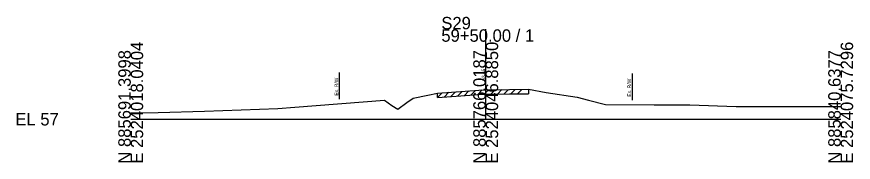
# Model space of a CAD drawing. Extents: x -26 to 163, y -10 to 4024.
# Drawn here: x -25.7 to 162.8, y 490.3 to 523.1 of the extents above; entities that cross this region are included whole.
import ezdxf

# ---------------------------------------------------------------- set-up
doc = ezdxf.new("R2010")
doc.units = 0
for name, color, linetype in [('RD_GPK_XS_Cell', 7, 'Continuous'), ('RD_XS_ExGround', 7, 'Continuous'), ('RD_XS_ExPaveRet', 7, 'Continuous'), ('RD_XS_ExRW', 7, 'Continuous'), ('RD_XS_TX_Elev_EX', 7, 'Continuous')]:
    doc.layers.add(name, color=color, linetype=linetype)

msp = doc.modelspace()

# ---------------------------------------------------------------- linework, layer by layer
at = {"layer": 'RD_GPK_XS_Cell'}
for p, q in [((80, 500), (80, 520.28)), ((0, 500), (80, 500)), ((80, 500), (160, 500))]:
    msp.add_line(p, q, dxfattribs=at)
at = {"layer": 'RD_XS_ExGround'}
for p, q in [((63.69, 504.78), (66.94, 505.42)), ((66.94, 505.42), (69.15, 505.92)), ((69.15, 505.92), (73.31, 506.18)), ((73.31, 506.18), (79.54, 506.64)), ((79.54, 506.64), (80, 506.65)), ((80, 506.65), (85.33, 506.72)), ((85.33, 506.72), (89.66, 506.76)), ((89.66, 506.76), (93.61, 506.05)), ((93.61, 506.05), (100.59, 505.02)), ((36.99, 502.76), (57.21, 504.34)), ((57.21, 504.34), (58.82, 503.14)), ((60.22, 502.25), (62.26, 503.75)), ((62.26, 503.75), (63.69, 504.78)), ((100.59, 505.02), (103.15, 504.31)), ((103.15, 504.31), (107.03, 503.34)), ((0, 501.47), (6.2, 501.52)), ((6.2, 501.52), (16.64, 501.86)), ((16.64, 501.86), (33.12, 502.41)), ((33.12, 502.41), (36.99, 502.76)), ((58.82, 503.14), (60.22, 502.25)), ((107.03, 503.34), (117.98, 503.29)), ((117.98, 503.29), (125.97, 503.29)), ((125.97, 503.29), (136.48, 502.85)), ((136.48, 502.85), (160, 502.89))]:
    msp.add_line(p, q, dxfattribs=at)
at = {"layer": 'RD_XS_ExPaveRet'}
for p, q in [((69.15, 504.92), (70.22, 505.99)), ((69.15, 504.92), (69.15, 505.92)), ((70.65, 505.01), (71.72, 506.08)), ((72.15, 505.11), (73.22, 506.18)), ((73.31, 505.18), (79.54, 505.64)), ((73.65, 505.21), (74.73, 506.29)), ((75.15, 505.32), (76.23, 506.4)), ((76.65, 505.43), (77.73, 506.51)), ((78.15, 505.54), (79.23, 506.62)), ((79.54, 505.64), (80, 505.65)), ((79.65, 505.64), (80.66, 506.65)), ((80, 505.65), (85.33, 505.72)), ((81.15, 505.66), (82.16, 506.67)), ((82.65, 505.68), (83.66, 506.69)), ((84.15, 505.7), (85.16, 506.71)), ((85.33, 505.72), (89.66, 505.76)), ((85.65, 505.72), (86.66, 506.73)), ((87.15, 505.73), (88.16, 506.74)), ((89.66, 506.76), (89.66, 505.76)), ((69.15, 504.92), (73.31, 505.18))]:
    msp.add_line(p, q, dxfattribs=at)
at = {"layer": 'RD_XS_ExRW'}
for p, q in [((47, 510.54), (47, 504.54)), ((113, 510.32), (113, 504.32))]:
    msp.add_line(p, q, dxfattribs=at)

# ---------------------------------------------------------------- texts
at = {"layer": 'RD_GPK_XS_Cell'}
for s, p in [('S29', (70, 520.28)), ('59+50.00 / 1', (70, 517.48)), ('EL 57', (-26, 498.6))]:
    msp.add_text(s, height=2.8, dxfattribs=at).set_placement(p)
for s, p in [('E 2524018.0404', (2.8, 490)), ('E 2524046.8850', (82.8, 490)), ('E 2524075.7296', (162.8, 490)), ('N 885691.3998', (0, 490)), ('N 885766.0187', (80, 490)), ('N 885840.6377', (160, 490))]:
    msp.add_text(s, height=2.8, rotation=90, dxfattribs=at).set_placement(p)
at = {"layer": 'RD_XS_ExRW'}
for p in [(46.75, 505.33), (112.75, 505.1)]:
    msp.add_text('Ex. R/W ', height=0.8, rotation=90, dxfattribs=at).set_placement(p)
at = {"layer": 'RD_XS_TX_Elev_EX'}
msp.add_text('63.65', height=0.8, rotation=90, dxfattribs=at).set_placement((79.9, 508.65))

doc.saveas('drawing.dxf')
